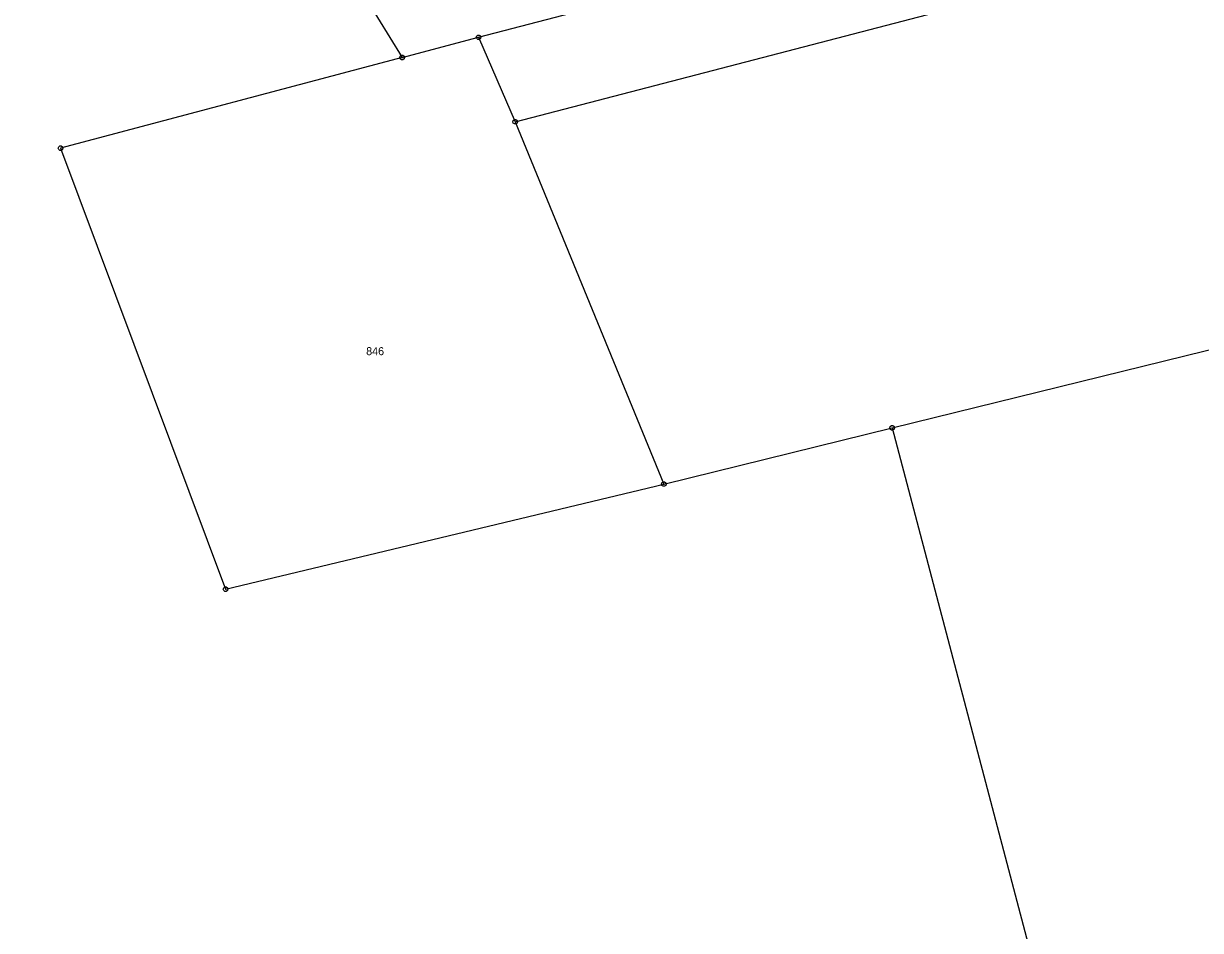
# Model space of a CAD drawing. Extents: x -871430 to -870620, y -1010094 to -1009649.
# Drawn here: x -871158.1 to -871095.6, y -1009905.2 to -1009857 of the extents above; entities that cross this region are included whole.
import ezdxf

# ---------------------------------------------------------------- set-up
doc = ezdxf.new("R2010")
doc.units = 0
for name, color, linetype in [('Vrstva 1', 7, 'Continuous'), ('Vrstva 2', 7, 'Continuous'), ('Vrstva 8', 7, 'Continuous')]:
    doc.layers.add(name, color=color, linetype=linetype)

msp = doc.modelspace()

# ---------------------------------------------------------------- linework, layer by layer
at = {"layer": 'Vrstva 1'}
for p, q in [((-871183.09, -1009785.71), (-871137.99, -1009858.82)), ((-871131.99, -1009862.23), (-871048.58, -1009840.53)), ((-871133.93, -1009857.75), (-871096.81, -1009848.03)), ((-871137.99, -1009858.82), (-871133.93, -1009857.75)), ((-871133.93, -1009857.75), (-871131.99, -1009862.23)), ((-871137.99, -1009858.82), (-871156.12, -1009863.63)), ((-871131.99, -1009862.23), (-871124.1, -1009881.46)), ((-871156.12, -1009863.63), (-871147.36, -1009887.04)), ((-871111.98, -1009878.48), (-871088.8, -1009872.78)), ((-871124.1, -1009881.46), (-871111.98, -1009878.48)), ((-871111.98, -1009878.48), (-871077.55, -1010009.01)), ((-871147.36, -1009887.04), (-871124.1, -1009881.46))]:
    msp.add_line(p, q, dxfattribs=at)
at = {"layer": 'Vrstva 8'}
for p, q in [((-871133.942, -1009857.75), (-871133.918, -1009857.75)), ((-871138.002, -1009858.82), (-871137.978, -1009858.82)), ((-871132.002, -1009862.23), (-871131.978, -1009862.23)), ((-871156.132, -1009863.63), (-871156.108, -1009863.63)), ((-871111.992, -1009878.48), (-871111.968, -1009878.48)), ((-871124.112, -1009881.46), (-871124.088, -1009881.46)), ((-871147.372, -1009887.04), (-871147.348, -1009887.04))]:
    msp.add_line(p, q, dxfattribs=at)
for points in [[(-871133.893, -1009857.63), (-871133.83, -1009857.678), (-871133.805, -1009857.75), (-871133.83, -1009857.822), (-871133.893, -1009857.87), (-871133.968, -1009857.87), (-871134.03, -1009857.822), (-871134.055, -1009857.75), (-871134.03, -1009857.678), (-871133.968, -1009857.63), (-871133.893, -1009857.63)], [(-871137.952, -1009858.7), (-871137.89, -1009858.747), (-871137.865, -1009858.82), (-871137.89, -1009858.892), (-871137.952, -1009858.94), (-871138.028, -1009858.94), (-871138.09, -1009858.892), (-871138.115, -1009858.82), (-871138.09, -1009858.747), (-871138.028, -1009858.7), (-871137.952, -1009858.7)], [(-871131.952, -1009862.11), (-871131.89, -1009862.158), (-871131.865, -1009862.23), (-871131.89, -1009862.302), (-871131.952, -1009862.35), (-871132.028, -1009862.35), (-871132.09, -1009862.302), (-871132.115, -1009862.23), (-871132.09, -1009862.158), (-871132.028, -1009862.11), (-871131.952, -1009862.11)], [(-871156.082, -1009863.51), (-871156.02, -1009863.558), (-871155.995, -1009863.63), (-871156.02, -1009863.702), (-871156.082, -1009863.75), (-871156.158, -1009863.75), (-871156.22, -1009863.702), (-871156.245, -1009863.63), (-871156.22, -1009863.558), (-871156.158, -1009863.51), (-871156.082, -1009863.51)], [(-871111.942, -1009878.36), (-871111.88, -1009878.408), (-871111.855, -1009878.48), (-871111.88, -1009878.552), (-871111.942, -1009878.6), (-871112.018, -1009878.6), (-871112.08, -1009878.552), (-871112.105, -1009878.48), (-871112.08, -1009878.408), (-871112.018, -1009878.36), (-871111.942, -1009878.36)], [(-871124.062, -1009881.34), (-871124, -1009881.388), (-871123.975, -1009881.46), (-871124, -1009881.532), (-871124.062, -1009881.58), (-871124.138, -1009881.58), (-871124.2, -1009881.532), (-871124.225, -1009881.46), (-871124.2, -1009881.388), (-871124.138, -1009881.34), (-871124.062, -1009881.34)], [(-871147.322, -1009886.92), (-871147.26, -1009886.968), (-871147.235, -1009887.04), (-871147.26, -1009887.112), (-871147.322, -1009887.16), (-871147.398, -1009887.16), (-871147.46, -1009887.112), (-871147.485, -1009887.04), (-871147.46, -1009886.968), (-871147.398, -1009886.92), (-871147.322, -1009886.92)]]:
    msp.add_lwpolyline(points, dxfattribs=at)

# ---------------------------------------------------------------- texts
at = {"layer": 'Vrstva 2'}
msp.add_text('846', height=0.425, dxfattribs=at).set_placement((-871139.897, -1009874.622))

doc.saveas('drawing.dxf')
